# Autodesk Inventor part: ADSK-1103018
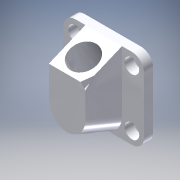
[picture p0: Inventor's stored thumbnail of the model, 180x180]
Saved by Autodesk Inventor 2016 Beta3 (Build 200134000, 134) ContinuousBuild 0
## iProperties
Shininess: 50.0
Length Units: 11272
Angle Units: 11279
Time Units: 11290
Mass Units: 11286
Length Display Precision: 4
Angle Display Precision: 2
Compacted: True
Created: 2000-09
Part Number: ADSK-1103018
Document SubType Name: Modeling
Description: INTAKE BODY
Mass: 1.50386 g
Surface Area: 7.7204 cm^2
Volume: 0.554931 cm^3
Density: 2.71 g/cm^3
Material: Aluminum-6061
Appearance: Aluminum - Flat
Density: 0.0
Volumn: 0.0
Area: 0.0
PropertySet Name: Model Information
Control State: 0
Master: False
Checked Out: False
Author: Autodesk, Inc.
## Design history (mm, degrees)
node "Extrusion1" dims "d2" = 1.5875, "d3" = 0
  sketch "Sketch3"
    geometry: L1 (-6.985, 4.889)-(-6.985, -4.889); L2 (6.985, -4.889)-(6.985, 4.889); L3 (4.889, 6.985)-(-4.889, 6.985); L4 (-4.889, -6.985)-(4.889, -6.985); A1 r 2.096 centre (-4.889, 4.889) between (-4.889, 6.985) and (-6.985, 4.889); A2 r 2.096 centre (-4.889, -4.889) between (-6.985, -4.889) and (-4.889, -6.985); A3 r 2.096 centre (4.889, -4.889) between (4.889, -6.985) and (6.985, -4.889); A4 r 2.095 centre (4.889, 4.889) between (6.985, 4.889) and (4.889, 6.985)
    constraints: 8 end point, 8 point on circle, 6 tangent, 4 centre point, 3 equal radius, 3 perpendicular, 1 horizontal, 1 parallel, 1 vertical, 1 other
    dimensions: "d0" = 13.97 distance between parallel lines of L2 L1; "d1" = 2.0955 radius of A2
node "Extrusion2" dims "d5" = 1.5875, "d6" = 0
  sketch "Sketch4"
    geometry: C1 r 1.27 at (-4.889, 4.889); C2 r 1.27 at (4.889, 4.889); C3 r 1.27 at (4.889, -4.889); C4 r 1.27 at (-4.889, -4.889); 4 further points
    constraints: 4 centre point, 4 coincident, 3 equal radius
    dimensions: "d4" = 2.54 diameter of C4
workplane "Work Plane1"
workplane "Work Plane2"
node "Extrusion3" dims "d11" = 1.5875, "d12" = 0
  sketch "Sketch5"
    geometry: L1 (1.587, 9.779)-(1.587, 0) reference; L2 (0, 11.874)-(1.587, 11.874) reference; L3 (0, -2.096)-(1.587, -2.096) reference; L4 (1.587, 11.874)-(1.587, -2.096); L5 (1.587, -2.096)-(7.938, 0.535); L6 (7.938, 0.535)-(7.938, 9.244); L7 (7.938, 9.244)-(1.587, 11.874)
    constraints: 8 end point, 1 collinear, 1 equal length, 1 parallel
    dimensions: "d9" = 45 deg angle of L5 L7; "d10" = 6.35 distance between parallel lines of L1 L6
node "Fillet1" dims "d15" = 3.175
node "Hole2" dims "d42" = 4.7625, "d43" = 9.525, "d44" = 6.35, "d45" = 60 deg, "d46" = 7.62, "d47" = 118 deg
  sketch "Sketch10"
    geometry: L1 (0, 0)-(6.35, 0) reference; L2 (0, -6.873)-(0, 0) reference; 1 further point
    dimensions: "d40" = 3.81 distance from line of L1 point (3.175, -3.81); "d41" = 3.175 distance from line of L2 point (3.175, -3.81)
body "Solid1"
other parameters: "d7" = -3.81, "d8" = -3.81
